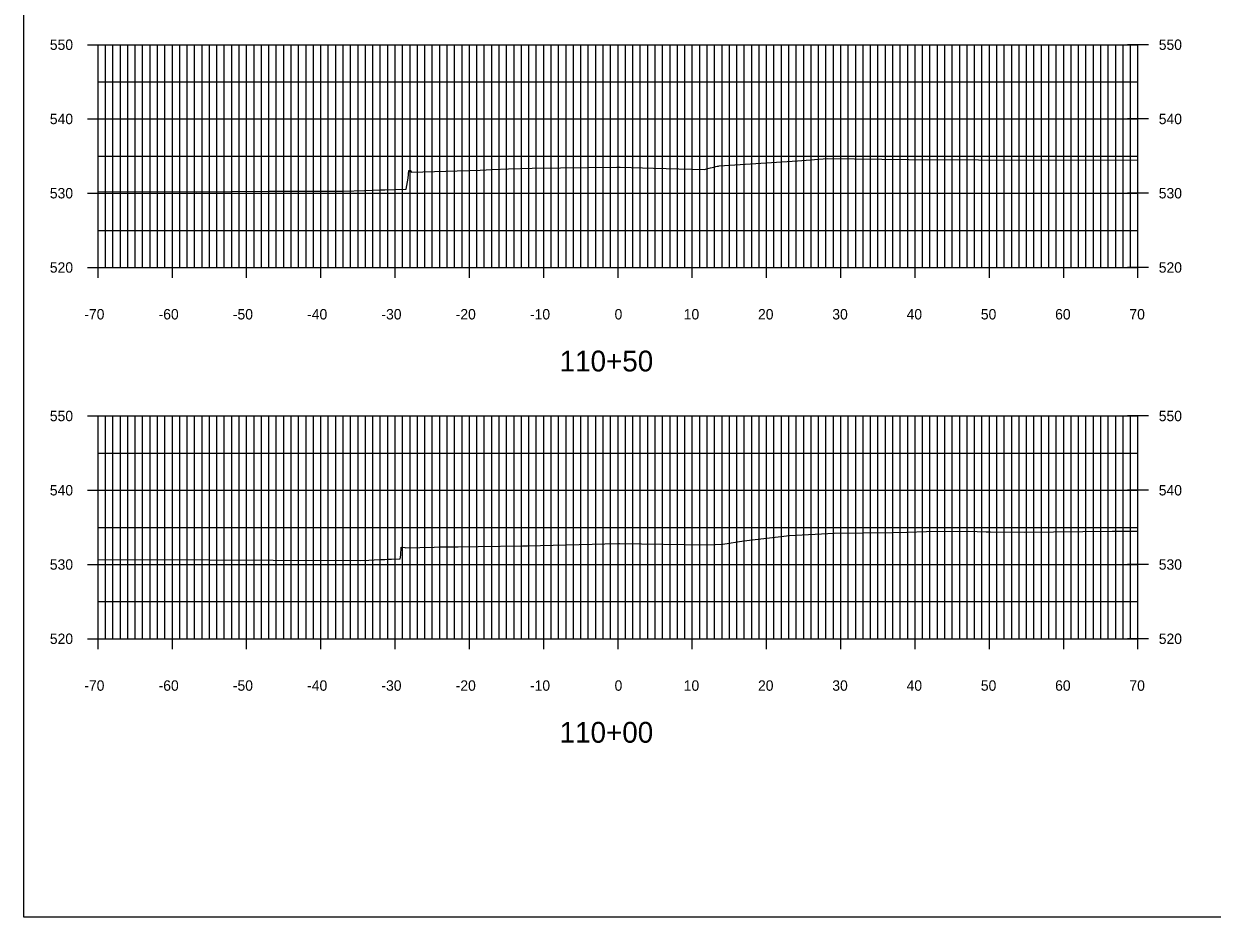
# Model space of a CAD drawing. Extents: x 1509063 to 1512863, y 401160 to 402918.
# Drawn here: x 1512542.7 to 1512702.7, y 402252.1 to 402372.4 of the extents above; entities that cross this region are included whole.
import ezdxf

# ---------------------------------------------------------------- set-up
doc = ezdxf.new("R2010")
doc.units = 0
for name, color, linetype in [('NBL1', 7, 'Continuous'), ('XAX_P', 7, 'Continuous'), ('XAXTIC_P', 7, 'Continuous'), ('XAXTXT_P_T', 7, 'Continuous'), ('XGL_P', 7, 'Continuous'), ('XSLOG', 7, 'Continuous')]:
    doc.layers.add(name, color=color, linetype=linetype)

msp = doc.modelspace()

# ---------------------------------------------------------------- linework, layer by layer
at = {"layer": 'NBL1'}
msp.add_lwpolyline([(1512862.73, 402252.08), (1512542.73, 402252.08), (1512542.73, 402462.08), (1512862.73, 402462.08)], close=True, dxfattribs=at)
at = {"layer": 'XAX_P'}
for p, q in [((1512552.73, 402339.58), (1512552.73, 402369.58)), ((1512622.73, 402339.58), (1512622.73, 402369.58)), ((1512692.73, 402339.58), (1512692.73, 402369.58)), ((1512552.73, 402339.58), (1512692.73, 402339.58)), ((1512552.73, 402289.58), (1512552.73, 402319.58)), ((1512622.73, 402289.58), (1512622.73, 402319.58)), ((1512692.73, 402289.58), (1512692.73, 402319.58)), ((1512552.73, 402289.58), (1512692.73, 402289.58))]:
    msp.add_line(p, q, dxfattribs=at)
at = {"layer": 'XAXTIC_P'}
for p, q in [((1512551.33, 402369.58), (1512554.13, 402369.58)), ((1512621.33, 402369.58), (1512624.13, 402369.58)), ((1512694.13, 402369.58), (1512691.33, 402369.58)), ((1512551.33, 402359.58), (1512554.13, 402359.58)), ((1512621.33, 402359.58), (1512624.13, 402359.58)), ((1512694.13, 402359.58), (1512691.33, 402359.58)), ((1512551.33, 402349.58), (1512554.13, 402349.58)), ((1512621.33, 402349.58), (1512624.13, 402349.58)), ((1512694.13, 402349.58), (1512691.33, 402349.58)), ((1512552.73, 402338.18), (1512552.73, 402340.98)), ((1512562.73, 402338.18), (1512562.73, 402340.98)), ((1512572.73, 402338.18), (1512572.73, 402340.98)), ((1512582.73, 402338.18), (1512582.73, 402340.98)), ((1512592.73, 402338.18), (1512592.73, 402340.98)), ((1512602.73, 402338.18), (1512602.73, 402340.98)), ((1512612.73, 402338.18), (1512612.73, 402340.98)), ((1512622.73, 402338.18), (1512622.73, 402340.98)), ((1512632.73, 402338.18), (1512632.73, 402340.98)), ((1512642.73, 402338.18), (1512642.73, 402340.98)), ((1512652.73, 402338.18), (1512652.73, 402340.98)), ((1512662.73, 402338.18), (1512662.73, 402340.98)), ((1512672.73, 402338.18), (1512672.73, 402340.98)), ((1512682.73, 402338.18), (1512682.73, 402340.98)), ((1512692.73, 402338.18), (1512692.73, 402340.98)), ((1512551.33, 402339.58), (1512554.13, 402339.58)), ((1512621.33, 402339.58), (1512624.13, 402339.58)), ((1512694.13, 402339.58), (1512691.33, 402339.58)), ((1512551.33, 402319.58), (1512554.13, 402319.58)), ((1512621.33, 402319.58), (1512624.13, 402319.58)), ((1512694.13, 402319.58), (1512691.33, 402319.58)), ((1512551.33, 402309.58), (1512554.13, 402309.58)), ((1512621.33, 402309.58), (1512624.13, 402309.58)), ((1512694.13, 402309.58), (1512691.33, 402309.58)), ((1512551.33, 402299.58), (1512554.13, 402299.58)), ((1512621.33, 402299.58), (1512624.13, 402299.58)), ((1512694.13, 402299.58), (1512691.33, 402299.58)), ((1512552.73, 402288.18), (1512552.73, 402290.98)), ((1512562.73, 402288.18), (1512562.73, 402290.98)), ((1512572.73, 402288.18), (1512572.73, 402290.98)), ((1512582.73, 402288.18), (1512582.73, 402290.98)), ((1512592.73, 402288.18), (1512592.73, 402290.98)), ((1512602.73, 402288.18), (1512602.73, 402290.98)), ((1512612.73, 402288.18), (1512612.73, 402290.98)), ((1512622.73, 402288.18), (1512622.73, 402290.98)), ((1512632.73, 402288.18), (1512632.73, 402290.98)), ((1512642.73, 402288.18), (1512642.73, 402290.98)), ((1512652.73, 402288.18), (1512652.73, 402290.98)), ((1512662.73, 402288.18), (1512662.73, 402290.98)), ((1512672.73, 402288.18), (1512672.73, 402290.98)), ((1512682.73, 402288.18), (1512682.73, 402290.98)), ((1512692.73, 402288.18), (1512692.73, 402290.98)), ((1512551.33, 402289.58), (1512554.13, 402289.58)), ((1512621.33, 402289.58), (1512624.13, 402289.58)), ((1512694.13, 402289.58), (1512691.33, 402289.58))]:
    msp.add_line(p, q, dxfattribs=at)
at = {"layer": 'XGL_P'}
for p, q in [((1512552.73, 402369.58), (1512692.73, 402369.58)), ((1512552.73, 402339.58), (1512552.73, 402369.58)), ((1512553.73, 402339.58), (1512553.73, 402369.58)), ((1512554.73, 402339.58), (1512554.73, 402369.58)), ((1512555.73, 402339.58), (1512555.73, 402369.58)), ((1512556.73, 402339.58), (1512556.73, 402369.58)), ((1512557.73, 402339.58), (1512557.73, 402369.58)), ((1512558.73, 402339.58), (1512558.73, 402369.58)), ((1512559.73, 402339.58), (1512559.73, 402369.58)), ((1512560.73, 402339.58), (1512560.73, 402369.58)), ((1512561.73, 402339.58), (1512561.73, 402369.58)), ((1512562.73, 402339.58), (1512562.73, 402369.58)), ((1512563.73, 402339.58), (1512563.73, 402369.58)), ((1512564.73, 402339.58), (1512564.73, 402369.58)), ((1512565.73, 402339.58), (1512565.73, 402369.58)), ((1512566.73, 402339.58), (1512566.73, 402369.58)), ((1512567.73, 402339.58), (1512567.73, 402369.58)), ((1512568.73, 402339.58), (1512568.73, 402369.58)), ((1512569.73, 402339.58), (1512569.73, 402369.58)), ((1512570.73, 402339.58), (1512570.73, 402369.58)), ((1512571.73, 402339.58), (1512571.73, 402369.58)), ((1512572.73, 402339.58), (1512572.73, 402369.58)), ((1512573.73, 402339.58), (1512573.73, 402369.58)), ((1512574.73, 402339.58), (1512574.73, 402369.58)), ((1512575.73, 402339.58), (1512575.73, 402369.58)), ((1512576.73, 402339.58), (1512576.73, 402369.58)), ((1512577.73, 402339.58), (1512577.73, 402369.58)), ((1512578.73, 402339.58), (1512578.73, 402369.58)), ((1512579.73, 402339.58), (1512579.73, 402369.58)), ((1512580.73, 402339.58), (1512580.73, 402369.58)), ((1512581.73, 402339.58), (1512581.73, 402369.58)), ((1512582.73, 402339.58), (1512582.73, 402369.58)), ((1512583.73, 402339.58), (1512583.73, 402369.58)), ((1512584.73, 402339.58), (1512584.73, 402369.58)), ((1512585.73, 402339.58), (1512585.73, 402369.58)), ((1512586.73, 402339.58), (1512586.73, 402369.58)), ((1512587.73, 402339.58), (1512587.73, 402369.58)), ((1512588.73, 402339.58), (1512588.73, 402369.58)), ((1512589.73, 402339.58), (1512589.73, 402369.58)), ((1512590.73, 402339.58), (1512590.73, 402369.58)), ((1512591.73, 402339.58), (1512591.73, 402369.58)), ((1512592.73, 402339.58), (1512592.73, 402369.58)), ((1512593.73, 402339.58), (1512593.73, 402369.58)), ((1512594.73, 402339.58), (1512594.73, 402369.58)), ((1512595.73, 402339.58), (1512595.73, 402369.58)), ((1512596.73, 402339.58), (1512596.73, 402369.58)), ((1512597.73, 402339.58), (1512597.73, 402369.58)), ((1512598.73, 402339.58), (1512598.73, 402369.58)), ((1512599.73, 402339.58), (1512599.73, 402369.58)), ((1512600.73, 402339.58), (1512600.73, 402369.58)), ((1512601.73, 402339.58), (1512601.73, 402369.58)), ((1512602.73, 402339.58), (1512602.73, 402369.58)), ((1512603.73, 402339.58), (1512603.73, 402369.58)), ((1512604.73, 402339.58), (1512604.73, 402369.58)), ((1512605.73, 402339.58), (1512605.73, 402369.58)), ((1512606.73, 402339.58), (1512606.73, 402369.58)), ((1512607.73, 402339.58), (1512607.73, 402369.58)), ((1512608.73, 402339.58), (1512608.73, 402369.58)), ((1512609.73, 402339.58), (1512609.73, 402369.58)), ((1512610.73, 402339.58), (1512610.73, 402369.58)), ((1512611.73, 402339.58), (1512611.73, 402369.58)), ((1512612.73, 402339.58), (1512612.73, 402369.58)), ((1512613.73, 402339.58), (1512613.73, 402369.58)), ((1512614.73, 402339.58), (1512614.73, 402369.58)), ((1512615.73, 402339.58), (1512615.73, 402369.58)), ((1512616.73, 402339.58), (1512616.73, 402369.58)), ((1512617.73, 402339.58), (1512617.73, 402369.58)), ((1512618.73, 402339.58), (1512618.73, 402369.58)), ((1512619.73, 402339.58), (1512619.73, 402369.58)), ((1512620.73, 402339.58), (1512620.73, 402369.58)), ((1512621.73, 402339.58), (1512621.73, 402369.58)), ((1512622.73, 402339.58), (1512622.73, 402369.58)), ((1512623.73, 402339.58), (1512623.73, 402369.58)), ((1512624.73, 402339.58), (1512624.73, 402369.58)), ((1512625.73, 402339.58), (1512625.73, 402369.58)), ((1512626.73, 402339.58), (1512626.73, 402369.58)), ((1512627.73, 402339.58), (1512627.73, 402369.58)), ((1512628.73, 402339.58), (1512628.73, 402369.58)), ((1512629.73, 402339.58), (1512629.73, 402369.58)), ((1512630.73, 402339.58), (1512630.73, 402369.58)), ((1512631.73, 402339.58), (1512631.73, 402369.58)), ((1512632.73, 402339.58), (1512632.73, 402369.58)), ((1512633.73, 402339.58), (1512633.73, 402369.58)), ((1512634.73, 402339.58), (1512634.73, 402369.58)), ((1512635.73, 402339.58), (1512635.73, 402369.58)), ((1512636.73, 402339.58), (1512636.73, 402369.58)), ((1512637.73, 402339.58), (1512637.73, 402369.58)), ((1512638.73, 402339.58), (1512638.73, 402369.58)), ((1512639.73, 402339.58), (1512639.73, 402369.58)), ((1512640.73, 402339.58), (1512640.73, 402369.58)), ((1512641.73, 402339.58), (1512641.73, 402369.58)), ((1512642.73, 402339.58), (1512642.73, 402369.58)), ((1512643.73, 402339.58), (1512643.73, 402369.58)), ((1512644.73, 402339.58), (1512644.73, 402369.58)), ((1512645.73, 402339.58), (1512645.73, 402369.58)), ((1512646.73, 402339.58), (1512646.73, 402369.58)), ((1512647.73, 402339.58), (1512647.73, 402369.58)), ((1512648.73, 402339.58), (1512648.73, 402369.58)), ((1512649.73, 402339.58), (1512649.73, 402369.58)), ((1512650.73, 402339.58), (1512650.73, 402369.58)), ((1512651.73, 402339.58), (1512651.73, 402369.58)), ((1512652.73, 402339.58), (1512652.73, 402369.58)), ((1512653.73, 402339.58), (1512653.73, 402369.58)), ((1512654.73, 402339.58), (1512654.73, 402369.58)), ((1512655.73, 402339.58), (1512655.73, 402369.58)), ((1512656.73, 402339.58), (1512656.73, 402369.58)), ((1512657.73, 402339.58), (1512657.73, 402369.58)), ((1512658.73, 402339.58), (1512658.73, 402369.58)), ((1512659.73, 402339.58), (1512659.73, 402369.58)), ((1512660.73, 402339.58), (1512660.73, 402369.58)), ((1512661.73, 402339.58), (1512661.73, 402369.58)), ((1512662.73, 402339.58), (1512662.73, 402369.58)), ((1512663.73, 402339.58), (1512663.73, 402369.58)), ((1512664.73, 402339.58), (1512664.73, 402369.58)), ((1512665.73, 402339.58), (1512665.73, 402369.58)), ((1512666.73, 402339.58), (1512666.73, 402369.58)), ((1512667.73, 402339.58), (1512667.73, 402369.58)), ((1512668.73, 402339.58), (1512668.73, 402369.58)), ((1512669.73, 402339.58), (1512669.73, 402369.58)), ((1512670.73, 402339.58), (1512670.73, 402369.58)), ((1512671.73, 402339.58), (1512671.73, 402369.58)), ((1512672.73, 402339.58), (1512672.73, 402369.58)), ((1512673.73, 402339.58), (1512673.73, 402369.58)), ((1512674.73, 402339.58), (1512674.73, 402369.58)), ((1512675.73, 402339.58), (1512675.73, 402369.58)), ((1512676.73, 402339.58), (1512676.73, 402369.58)), ((1512677.73, 402339.58), (1512677.73, 402369.58)), ((1512678.73, 402339.58), (1512678.73, 402369.58)), ((1512679.73, 402339.58), (1512679.73, 402369.58)), ((1512680.73, 402339.58), (1512680.73, 402369.58)), ((1512681.73, 402339.58), (1512681.73, 402369.58)), ((1512682.73, 402339.58), (1512682.73, 402369.58)), ((1512683.73, 402339.58), (1512683.73, 402369.58)), ((1512684.73, 402339.58), (1512684.73, 402369.58)), ((1512685.73, 402339.58), (1512685.73, 402369.58)), ((1512686.73, 402339.58), (1512686.73, 402369.58)), ((1512687.73, 402339.58), (1512687.73, 402369.58)), ((1512688.73, 402339.58), (1512688.73, 402369.58)), ((1512689.73, 402339.58), (1512689.73, 402369.58)), ((1512690.73, 402339.58), (1512690.73, 402369.58)), ((1512691.73, 402339.58), (1512691.73, 402369.58)), ((1512692.73, 402339.58), (1512692.73, 402369.58)), ((1512552.73, 402364.58), (1512692.73, 402364.58)), ((1512552.73, 402359.58), (1512692.73, 402359.58)), ((1512552.73, 402354.58), (1512692.73, 402354.58)), ((1512552.73, 402349.58), (1512692.73, 402349.58)), ((1512552.73, 402344.58), (1512692.73, 402344.58)), ((1512552.73, 402339.58), (1512692.73, 402339.58)), ((1512552.73, 402319.58), (1512692.73, 402319.58)), ((1512552.73, 402289.58), (1512552.73, 402319.58)), ((1512553.73, 402289.58), (1512553.73, 402319.58)), ((1512554.73, 402289.58), (1512554.73, 402319.58)), ((1512555.73, 402289.58), (1512555.73, 402319.58)), ((1512556.73, 402289.58), (1512556.73, 402319.58)), ((1512557.73, 402289.58), (1512557.73, 402319.58)), ((1512558.73, 402289.58), (1512558.73, 402319.58)), ((1512559.73, 402289.58), (1512559.73, 402319.58)), ((1512560.73, 402289.58), (1512560.73, 402319.58)), ((1512561.73, 402289.58), (1512561.73, 402319.58)), ((1512562.73, 402289.58), (1512562.73, 402319.58)), ((1512563.73, 402289.58), (1512563.73, 402319.58)), ((1512564.73, 402289.58), (1512564.73, 402319.58)), ((1512565.73, 402289.58), (1512565.73, 402319.58)), ((1512566.73, 402289.58), (1512566.73, 402319.58)), ((1512567.73, 402289.58), (1512567.73, 402319.58)), ((1512568.73, 402289.58), (1512568.73, 402319.58)), ((1512569.73, 402289.58), (1512569.73, 402319.58)), ((1512570.73, 402289.58), (1512570.73, 402319.58)), ((1512571.73, 402289.58), (1512571.73, 402319.58)), ((1512572.73, 402289.58), (1512572.73, 402319.58)), ((1512573.73, 402289.58), (1512573.73, 402319.58)), ((1512574.73, 402289.58), (1512574.73, 402319.58)), ((1512575.73, 402289.58), (1512575.73, 402319.58)), ((1512576.73, 402289.58), (1512576.73, 402319.58)), ((1512577.73, 402289.58), (1512577.73, 402319.58)), ((1512578.73, 402289.58), (1512578.73, 402319.58)), ((1512579.73, 402289.58), (1512579.73, 402319.58)), ((1512580.73, 402289.58), (1512580.73, 402319.58)), ((1512581.73, 402289.58), (1512581.73, 402319.58)), ((1512582.73, 402289.58), (1512582.73, 402319.58)), ((1512583.73, 402289.58), (1512583.73, 402319.58)), ((1512584.73, 402289.58), (1512584.73, 402319.58)), ((1512585.73, 402289.58), (1512585.73, 402319.58)), ((1512586.73, 402289.58), (1512586.73, 402319.58)), ((1512587.73, 402289.58), (1512587.73, 402319.58)), ((1512588.73, 402289.58), (1512588.73, 402319.58)), ((1512589.73, 402289.58), (1512589.73, 402319.58)), ((1512590.73, 402289.58), (1512590.73, 402319.58)), ((1512591.73, 402289.58), (1512591.73, 402319.58)), ((1512592.73, 402289.58), (1512592.73, 402319.58)), ((1512593.73, 402289.58), (1512593.73, 402319.58)), ((1512594.73, 402289.58), (1512594.73, 402319.58)), ((1512595.73, 402289.58), (1512595.73, 402319.58)), ((1512596.73, 402289.58), (1512596.73, 402319.58)), ((1512597.73, 402289.58), (1512597.73, 402319.58)), ((1512598.73, 402289.58), (1512598.73, 402319.58)), ((1512599.73, 402289.58), (1512599.73, 402319.58)), ((1512600.73, 402289.58), (1512600.73, 402319.58)), ((1512601.73, 402289.58), (1512601.73, 402319.58)), ((1512602.73, 402289.58), (1512602.73, 402319.58)), ((1512603.73, 402289.58), (1512603.73, 402319.58)), ((1512604.73, 402289.58), (1512604.73, 402319.58)), ((1512605.73, 402289.58), (1512605.73, 402319.58)), ((1512606.73, 402289.58), (1512606.73, 402319.58)), ((1512607.73, 402289.58), (1512607.73, 402319.58)), ((1512608.73, 402289.58), (1512608.73, 402319.58)), ((1512609.73, 402289.58), (1512609.73, 402319.58)), ((1512610.73, 402289.58), (1512610.73, 402319.58)), ((1512611.73, 402289.58), (1512611.73, 402319.58)), ((1512612.73, 402289.58), (1512612.73, 402319.58)), ((1512613.73, 402289.58), (1512613.73, 402319.58)), ((1512614.73, 402289.58), (1512614.73, 402319.58)), ((1512615.73, 402289.58), (1512615.73, 402319.58)), ((1512616.73, 402289.58), (1512616.73, 402319.58)), ((1512617.73, 402289.58), (1512617.73, 402319.58)), ((1512618.73, 402289.58), (1512618.73, 402319.58)), ((1512619.73, 402289.58), (1512619.73, 402319.58)), ((1512620.73, 402289.58), (1512620.73, 402319.58)), ((1512621.73, 402289.58), (1512621.73, 402319.58)), ((1512622.73, 402289.58), (1512622.73, 402319.58)), ((1512623.73, 402289.58), (1512623.73, 402319.58)), ((1512624.73, 402289.58), (1512624.73, 402319.58)), ((1512625.73, 402289.58), (1512625.73, 402319.58)), ((1512626.73, 402289.58), (1512626.73, 402319.58)), ((1512627.73, 402289.58), (1512627.73, 402319.58)), ((1512628.73, 402289.58), (1512628.73, 402319.58)), ((1512629.73, 402289.58), (1512629.73, 402319.58)), ((1512630.73, 402289.58), (1512630.73, 402319.58)), ((1512631.73, 402289.58), (1512631.73, 402319.58)), ((1512632.73, 402289.58), (1512632.73, 402319.58)), ((1512633.73, 402289.58), (1512633.73, 402319.58)), ((1512634.73, 402289.58), (1512634.73, 402319.58)), ((1512635.73, 402289.58), (1512635.73, 402319.58)), ((1512636.73, 402289.58), (1512636.73, 402319.58)), ((1512637.73, 402289.58), (1512637.73, 402319.58)), ((1512638.73, 402289.58), (1512638.73, 402319.58)), ((1512639.73, 402289.58), (1512639.73, 402319.58)), ((1512640.73, 402289.58), (1512640.73, 402319.58)), ((1512641.73, 402289.58), (1512641.73, 402319.58)), ((1512642.73, 402289.58), (1512642.73, 402319.58)), ((1512643.73, 402289.58), (1512643.73, 402319.58)), ((1512644.73, 402289.58), (1512644.73, 402319.58)), ((1512645.73, 402289.58), (1512645.73, 402319.58)), ((1512646.73, 402289.58), (1512646.73, 402319.58)), ((1512647.73, 402289.58), (1512647.73, 402319.58)), ((1512648.73, 402289.58), (1512648.73, 402319.58)), ((1512649.73, 402289.58), (1512649.73, 402319.58)), ((1512650.73, 402289.58), (1512650.73, 402319.58)), ((1512651.73, 402289.58), (1512651.73, 402319.58)), ((1512652.73, 402289.58), (1512652.73, 402319.58)), ((1512653.73, 402289.58), (1512653.73, 402319.58)), ((1512654.73, 402289.58), (1512654.73, 402319.58)), ((1512655.73, 402289.58), (1512655.73, 402319.58)), ((1512656.73, 402289.58), (1512656.73, 402319.58)), ((1512657.73, 402289.58), (1512657.73, 402319.58)), ((1512658.73, 402289.58), (1512658.73, 402319.58)), ((1512659.73, 402289.58), (1512659.73, 402319.58)), ((1512660.73, 402289.58), (1512660.73, 402319.58)), ((1512661.73, 402289.58), (1512661.73, 402319.58)), ((1512662.73, 402289.58), (1512662.73, 402319.58)), ((1512663.73, 402289.58), (1512663.73, 402319.58)), ((1512664.73, 402289.58), (1512664.73, 402319.58)), ((1512665.73, 402289.58), (1512665.73, 402319.58)), ((1512666.73, 402289.58), (1512666.73, 402319.58)), ((1512667.73, 402289.58), (1512667.73, 402319.58)), ((1512668.73, 402289.58), (1512668.73, 402319.58)), ((1512669.73, 402289.58), (1512669.73, 402319.58)), ((1512670.73, 402289.58), (1512670.73, 402319.58)), ((1512671.73, 402289.58), (1512671.73, 402319.58)), ((1512672.73, 402289.58), (1512672.73, 402319.58)), ((1512673.73, 402289.58), (1512673.73, 402319.58)), ((1512674.73, 402289.58), (1512674.73, 402319.58)), ((1512675.73, 402289.58), (1512675.73, 402319.58)), ((1512676.73, 402289.58), (1512676.73, 402319.58)), ((1512677.73, 402289.58), (1512677.73, 402319.58)), ((1512678.73, 402289.58), (1512678.73, 402319.58)), ((1512679.73, 402289.58), (1512679.73, 402319.58)), ((1512680.73, 402289.58), (1512680.73, 402319.58)), ((1512681.73, 402289.58), (1512681.73, 402319.58)), ((1512682.73, 402289.58), (1512682.73, 402319.58)), ((1512683.73, 402289.58), (1512683.73, 402319.58)), ((1512684.73, 402289.58), (1512684.73, 402319.58)), ((1512685.73, 402289.58), (1512685.73, 402319.58)), ((1512686.73, 402289.58), (1512686.73, 402319.58)), ((1512687.73, 402289.58), (1512687.73, 402319.58)), ((1512688.73, 402289.58), (1512688.73, 402319.58)), ((1512689.73, 402289.58), (1512689.73, 402319.58)), ((1512690.73, 402289.58), (1512690.73, 402319.58)), ((1512691.73, 402289.58), (1512691.73, 402319.58)), ((1512692.73, 402289.58), (1512692.73, 402319.58)), ((1512552.73, 402314.58), (1512692.73, 402314.58)), ((1512552.73, 402309.58), (1512692.73, 402309.58)), ((1512552.73, 402304.58), (1512692.73, 402304.58)), ((1512552.73, 402299.58), (1512692.73, 402299.58)), ((1512552.73, 402294.58), (1512692.73, 402294.58)), ((1512552.73, 402289.58), (1512692.73, 402289.58))]:
    msp.add_line(p, q, dxfattribs=at)
at = {"layer": 'XSLOG'}
for points in [[(1512552.73, 402349.8), (1512565.95, 402349.78), (1512575.65, 402349.84), (1512585.78, 402349.87), (1512588.59, 402349.96), (1512590.81, 402350.04), (1512591.36, 402350.05), (1512594.21, 402350.12), (1512594.47, 402351.62), (1512594.59, 402352.64), (1512594.74, 402352.62), (1512594.95, 402352.42), (1512604.19, 402352.7), (1512605.8, 402352.78), (1512608, 402352.85), (1512611.16, 402352.96), (1512622.59, 402353.08), (1512623.01, 402353.08), (1512627.51, 402352.96), (1512634.31, 402352.77), (1512635.17, 402352.98), (1512635.64, 402353.1), (1512635.92, 402353.16), (1512636.1, 402353.21), (1512636.24, 402353.24), (1512636.34, 402353.27), (1512646.91, 402353.94), (1512650.94, 402354.26), (1512661.87, 402354.13), (1512671.25, 402354.08), (1512692.73, 402354.02)], [(1512552.73, 402300.27), (1512567.71, 402300.2), (1512576.31, 402300.17), (1512588.05, 402300.14), (1512589.19, 402300.18), (1512590.61, 402300.24), (1512591.32, 402300.27), (1512591.74, 402300.29), (1512592.03, 402300.3), (1512592.23, 402300.31), (1512593.41, 402300.34), (1512593.49, 402300.83), (1512593.54, 402301.92), (1512594.05, 402301.87), (1512594.11, 402301.81), (1512597.99, 402301.93), (1512598.68, 402301.94), (1512599.67, 402301.95), (1512601.2, 402301.97), (1512603.89, 402302.01), (1512609.89, 402302.09), (1512610.21, 402302.11), (1512610.54, 402302.1), (1512622.72, 402302.41), (1512622.83, 402302.41), (1512622.93, 402302.41), (1512634.73, 402302.24), (1512634.8, 402302.25), (1512636.85, 402302.33), (1512639.66, 402302.75), (1512645.8, 402303.49), (1512651.84, 402303.81), (1512659.76, 402303.9), (1512661.62, 402303.92), (1512664.26, 402304.01), (1512669.86, 402304.06), (1512672.31, 402303.97), (1512672.86, 402303.98), (1512677.4, 402303.95), (1512689.27, 402304.06), (1512692.73, 402304.07)]]:
    msp.add_lwpolyline(points, dxfattribs=at)

# ---------------------------------------------------------------- texts
at = {"layer": 'XAXTXT_P_T'}
for s, height, p in [('550', 1.4, (1512546.24, 402368.88)), ('550', 1.4, (1512695.53, 402368.88)), ('540', 1.4, (1512546.24, 402358.88)), ('540', 1.4, (1512695.53, 402358.88)), ('530', 1.4, (1512546.24, 402348.88)), ('530', 1.4, (1512695.53, 402348.88)), ('520', 1.4, (1512546.24, 402338.88)), ('520', 1.4, (1512695.53, 402338.88)), ('-70', 1.4, (1512550.88, 402332.58)), ('-60', 1.4, (1512560.88, 402332.58)), ('-50', 1.4, (1512570.88, 402332.58)), ('-40', 1.4, (1512580.88, 402332.58)), ('-30', 1.4, (1512590.88, 402332.58)), ('-20', 1.4, (1512600.88, 402332.58)), ('-10', 1.4, (1512610.88, 402332.58)), ('0', 1.4, (1512622.27, 402332.58)), ('10', 1.4, (1512631.58, 402332.58)), ('20', 1.4, (1512641.58, 402332.58)), ('30', 1.4, (1512651.58, 402332.58)), ('40', 1.4, (1512661.58, 402332.58)), ('50', 1.4, (1512671.58, 402332.58)), ('60', 1.4, (1512681.58, 402332.58)), ('70', 1.4, (1512691.58, 402332.58)), ('110+50', 2.8, (1512614.87, 402325.58)), ('550', 1.4, (1512546.24, 402318.88)), ('550', 1.4, (1512695.53, 402318.88)), ('540', 1.4, (1512546.24, 402308.88)), ('540', 1.4, (1512695.53, 402308.88)), ('530', 1.4, (1512546.24, 402298.88)), ('530', 1.4, (1512695.53, 402298.88)), ('520', 1.4, (1512546.24, 402288.88)), ('520', 1.4, (1512695.53, 402288.88)), ('-70', 1.4, (1512550.88, 402282.58)), ('-60', 1.4, (1512560.88, 402282.58)), ('-50', 1.4, (1512570.88, 402282.58)), ('-40', 1.4, (1512580.88, 402282.58)), ('-30', 1.4, (1512590.88, 402282.58)), ('-20', 1.4, (1512600.88, 402282.58)), ('-10', 1.4, (1512610.88, 402282.58)), ('0', 1.4, (1512622.27, 402282.58)), ('10', 1.4, (1512631.58, 402282.58)), ('20', 1.4, (1512641.58, 402282.58)), ('30', 1.4, (1512651.58, 402282.58)), ('40', 1.4, (1512661.58, 402282.58)), ('50', 1.4, (1512671.58, 402282.58)), ('60', 1.4, (1512681.58, 402282.58)), ('70', 1.4, (1512691.58, 402282.58)), ('110+00', 2.8, (1512614.87, 402275.58))]:
    msp.add_text(s, height=height, dxfattribs=at).set_placement(p)

doc.saveas('drawing.dxf')
